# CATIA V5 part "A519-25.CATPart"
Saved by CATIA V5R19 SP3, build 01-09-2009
Part number: A519-25
Bounding box of the stored display mesh (mm): x -12.468 to 12.468, y -12.468 to 12.468, z 0 to 45
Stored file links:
  C:\Users\d.catalano\Desktop\CATALOGO CAD\04 MOLLE\A519\A519-25.CATPart
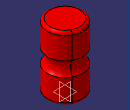
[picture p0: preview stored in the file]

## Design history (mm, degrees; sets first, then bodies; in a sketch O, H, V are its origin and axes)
Body1 "A519-25" (main body)
  Sketch1 on yz-plane, origin (0, 0, 0), H (0, 1, 0), V (0, 0, 1)
    line L1 (0, 0) -> (10.5, 0)
    line L2 (12.5, 2) -> (12.5, 17.4049)
    line L3 (10.5, 45) -> (0, 45)
    line L4 (0, 45) -> (0, 0)
    construction line L5 (-5.6038, 22.5) -> (28.5463, 22.5)
    arc A1 centre (17.3, 22.5) radius 7 from (12.5, 27.5951) to (12.5, 17.4049) ccw
    point P2 (17.3, 22.5)
    construction line L6 (10.3, 49.6338) -> (10.3, -12.4196)
    line L7 (12.5, 27.5951) -> (12.5, 43)
    arc A2 centre (10.5, 43) radius 2 from (10.5, 45) to (12.5, 43) cw
    arc A3 centre (10.5, 2) radius 2 from (10.5, 0) to (12.5, 2) ccw
    distance L4 L2 = 12.5
    distance L1 L3 = 45
    distance L5 L3 = 22.5
    radius A1 = 7
    distance L2 L6 = 2.2
    radius A2 = 2
    radius A3 = 2
    horizontal: L1 H, L3 H, L5 H
    vertical: L2 V, L4 V, L6 V, L7 V
    coincidence: P2 L5, L2 L7
    tangency: A1 L6, A2 L3, A2 L7, A3 L1, A3 L2
  Shaft1 "Albero": profile Sketch1, axis Sketch1.L4, angle 360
